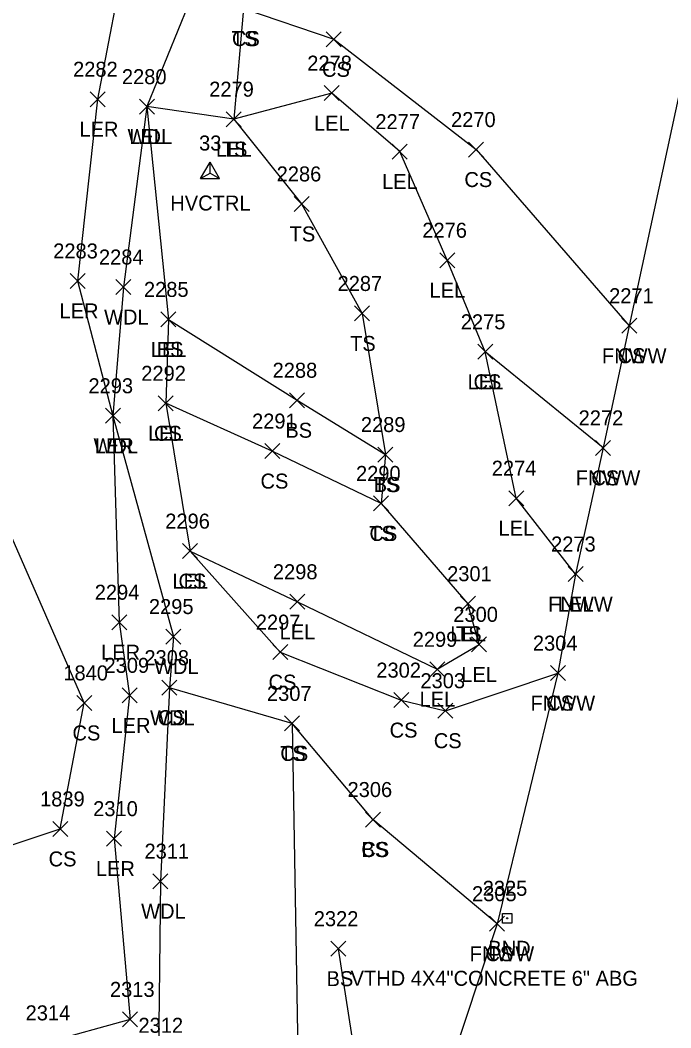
# Model space of a CAD drawing. Extents: x 1483143 to 1488182, y 802902 to 807581.
# Drawn here: x 1487923.7 to 1488010.4, y 806404.6 to 806539 of the extents above; entities that cross this region are included whole.
import ezdxf

# ---------------------------------------------------------------- set-up
doc = ezdxf.new("R2010")
doc.units = 0
for name, color, linetype in [('C_A', 7, 'Continuous'), ('C_I', 7, 'Continuous'), ('CPSM', 7, 'Continuous'), ('L_A', 7, 'Continuous'), ('L_I', 7, 'Continuous'), ('L_TIC', 7, 'Continuous'), ('LARO', 7, 'Continuous'), ('LAWA', 7, 'Continuous'), ('LELB', 7, 'Continuous'), ('LFNC', 7, 'Continuous'), ('M_A', 7, 'Continuous'), ('M_C', 7, 'Continuous'), ('M_I', 7, 'Continuous'), ('MHBP', 7, 'Continuous')]:
    doc.layers.add(name, color=color, linetype=linetype)

msp = doc.modelspace()

# ---------------------------------------------------------------- linework, layer by layer
at = {"layer": 'CPSM'}
for p, q in [((1487947.73, 806517.89), (1487948.98, 806520.06)), ((1487950.23, 806517.89), (1487948.98, 806520.06)), ((1487948.98, 806518.61), (1487948.98, 806520.06)), ((1487947.73, 806517.89), (1487948.98, 806518.61)), ((1487948.98, 806518.61), (1487948.98, 806518.61)), ((1487948.98, 806518.61), (1487950.23, 806517.89)), ((1487947.73, 806517.89), (1487950.23, 806517.89))]:
    msp.add_line(p, q, dxfattribs=at)
at = {"layer": 'L_TIC'}
for points in [[(1487964.47, 806535.44), (1487966.47, 806537.44)], [(1487966.47, 806535.44), (1487964.47, 806537.44)], [(1487964.2, 806528.26), (1487966.2, 806530.26)], [(1487966.2, 806528.26), (1487964.2, 806530.26)], [(1487932.98, 806527.45), (1487934.98, 806529.45)], [(1487934.98, 806527.45), (1487932.98, 806529.45)], [(1487939.57, 806526.46), (1487941.57, 806528.46)], [(1487941.57, 806526.46), (1487939.57, 806528.46)], [(1487939.57, 806526.46), (1487941.57, 806528.46)], [(1487941.57, 806526.46), (1487939.57, 806528.46)], [(1487951.14, 806524.79), (1487953.14, 806526.79)], [(1487953.14, 806524.79), (1487951.14, 806526.79)], [(1487951.14, 806524.79), (1487953.14, 806526.79)], [(1487953.14, 806524.79), (1487951.14, 806526.79)], [(1487973.28, 806520.46), (1487975.28, 806522.46)], [(1487975.28, 806520.46), (1487973.28, 806522.46)], [(1487983.45, 806520.74), (1487985.45, 806522.74)], [(1487985.45, 806520.74), (1487983.45, 806522.74)], [(1487960.18, 806513.49), (1487962.18, 806515.49)], [(1487962.18, 806513.49), (1487960.18, 806515.49)], [(1487979.6, 806505.98), (1487981.6, 806507.98)], [(1487981.6, 806505.98), (1487979.6, 806507.98)], [(1487930.33, 806503.22), (1487932.33, 806505.22)], [(1487932.33, 806503.22), (1487930.33, 806505.22)], [(1487936.43, 806502.41), (1487938.43, 806504.41)], [(1487938.43, 806502.41), (1487936.43, 806504.41)], [(1487968.24, 806498.88), (1487970.24, 806500.88)], [(1487970.24, 806498.88), (1487968.24, 806500.88)], [(1487942.43, 806498.09), (1487944.43, 806500.09)], [(1487944.43, 806498.09), (1487942.43, 806500.09)], [(1487942.43, 806498.09), (1487944.43, 806500.09)], [(1487944.43, 806498.09), (1487942.43, 806500.09)], [(1488003.88, 806497.25), (1488005.88, 806499.25)], [(1488005.88, 806497.25), (1488003.88, 806499.25)], [(1488003.88, 806497.25), (1488005.88, 806499.25)], [(1488005.88, 806497.25), (1488003.88, 806499.25)], [(1487984.67, 806493.77), (1487986.67, 806495.77)], [(1487986.67, 806493.77), (1487984.67, 806495.77)], [(1487984.67, 806493.77), (1487986.67, 806495.77)], [(1487986.67, 806493.77), (1487984.67, 806495.77)], [(1487942.07, 806486.9), (1487944.07, 806488.9)], [(1487944.07, 806486.9), (1487942.07, 806488.9)], [(1487942.07, 806486.9), (1487944.07, 806488.9)], [(1487944.07, 806486.9), (1487942.07, 806488.9)], [(1487959.58, 806487.31), (1487961.58, 806489.31)], [(1487961.58, 806487.31), (1487959.58, 806489.31)], [(1487935.03, 806485.24), (1487937.03, 806487.24)], [(1487937.03, 806485.24), (1487935.03, 806487.24)], [(1487935.03, 806485.24), (1487937.03, 806487.24)], [(1487937.03, 806485.24), (1487935.03, 806487.24)], [(1487956.27, 806480.53), (1487958.27, 806482.53)], [(1487958.27, 806480.53), (1487956.27, 806482.53)], [(1487971.36, 806480.07), (1487973.36, 806482.07)], [(1487973.36, 806480.07), (1487971.36, 806482.07)], [(1487971.36, 806480.07), (1487973.36, 806482.07)], [(1487973.36, 806480.07), (1487971.36, 806482.07)], [(1488000.38, 806480.96), (1488002.38, 806482.96)], [(1488002.38, 806480.96), (1488000.38, 806482.96)], [(1488000.38, 806480.96), (1488002.38, 806482.96)], [(1488002.38, 806480.96), (1488000.38, 806482.96)], [(1487970.79, 806473.55), (1487972.79, 806475.55)], [(1487972.79, 806473.55), (1487970.79, 806475.55)], [(1487970.79, 806473.55), (1487972.79, 806475.55)], [(1487972.79, 806473.55), (1487970.79, 806475.55)], [(1487988.8, 806474.25), (1487990.8, 806476.25)], [(1487990.8, 806474.25), (1487988.8, 806476.25)], [(1487945.33, 806467.19), (1487947.33, 806469.19)], [(1487947.33, 806467.19), (1487945.33, 806469.19)], [(1487945.33, 806467.19), (1487947.33, 806469.19)], [(1487947.33, 806467.19), (1487945.33, 806469.19)], [(1487996.71, 806464.14), (1487998.71, 806466.14)], [(1487998.71, 806464.14), (1487996.71, 806466.14)], [(1487996.71, 806464.14), (1487998.71, 806466.14)], [(1487998.71, 806464.14), (1487996.71, 806466.14)], [(1487959.62, 806460.44), (1487961.62, 806462.44)], [(1487961.62, 806460.44), (1487959.62, 806462.44)], [(1487982.36, 806460.18), (1487984.36, 806462.18)], [(1487984.36, 806460.18), (1487982.36, 806462.18)], [(1487982.36, 806460.18), (1487984.36, 806462.18)], [(1487984.36, 806460.18), (1487982.36, 806462.18)], [(1487935.87, 806457.71), (1487937.87, 806459.71)], [(1487937.87, 806457.71), (1487935.87, 806459.71)], [(1487943.09, 806455.8), (1487945.09, 806457.8)], [(1487945.09, 806455.8), (1487943.09, 806457.8)], [(1487983.84, 806454.76), (1487985.84, 806456.76)], [(1487985.84, 806454.76), (1487983.84, 806456.76)], [(1487957.34, 806453.72), (1487959.34, 806455.72)], [(1487959.34, 806453.72), (1487957.34, 806455.72)], [(1487978.27, 806451.43), (1487980.27, 806453.43)], [(1487980.27, 806451.43), (1487978.27, 806453.43)], [(1487994.36, 806450.92), (1487996.36, 806452.92)], [(1487996.36, 806450.92), (1487994.36, 806452.92)], [(1487994.36, 806450.92), (1487996.36, 806452.92)], [(1487996.36, 806450.92), (1487994.36, 806452.92)], [(1487942.56, 806448.98), (1487944.56, 806450.98)], [(1487944.56, 806448.98), (1487942.56, 806450.98)], [(1487942.56, 806448.98), (1487944.56, 806450.98)], [(1487944.56, 806448.98), (1487942.56, 806450.98)], [(1487937.26, 806447.96), (1487939.26, 806449.96)], [(1487939.26, 806447.96), (1487937.26, 806449.96)], [(1487931.2, 806446.95), (1487933.2, 806448.95)], [(1487933.2, 806446.95), (1487931.2, 806448.95)], [(1487973.48, 806447.32), (1487975.48, 806449.32)], [(1487975.48, 806447.32), (1487973.48, 806449.32)], [(1487979.36, 806445.91), (1487981.36, 806447.91)], [(1487981.36, 806445.91), (1487979.36, 806447.91)], [(1487958.91, 806444.22), (1487960.91, 806446.22)], [(1487960.91, 806444.22), (1487958.91, 806446.22)], [(1487958.91, 806444.22), (1487960.91, 806446.22)], [(1487960.91, 806444.22), (1487958.91, 806446.22)], [(1487969.7, 806431.4), (1487971.7, 806433.4)], [(1487971.7, 806431.4), (1487969.7, 806433.4)], [(1487969.7, 806431.4), (1487971.7, 806433.4)], [(1487971.7, 806431.4), (1487969.7, 806433.4)], [(1487928.02, 806430.15), (1487930.02, 806432.15)], [(1487930.02, 806430.15), (1487928.02, 806432.15)], [(1487935.18, 806428.85), (1487937.18, 806430.85)], [(1487937.18, 806428.85), (1487935.18, 806430.85)], [(1487941.37, 806423.18), (1487943.37, 806425.18)], [(1487943.37, 806423.18), (1487941.37, 806425.18)], [(1487986.25, 806417.51), (1487988.25, 806419.51)], [(1487988.25, 806417.51), (1487986.25, 806419.51)], [(1487986.25, 806417.51), (1487988.25, 806419.51)], [(1487988.25, 806417.51), (1487986.25, 806419.51)], [(1487965.07, 806414.18), (1487967.07, 806416.18)], [(1487967.07, 806414.18), (1487965.07, 806416.18)], [(1487937.33, 806404.75), (1487939.33, 806406.75)], [(1487939.33, 806404.75), (1487937.33, 806406.75)]]:
    msp.add_lwpolyline(points, dxfattribs=at)
at = {"layer": 'LARO'}
for points in [[(1488009.53, 806779.63), (1488008.11, 806762.07), (1487997.19, 806745.28), (1487993.76, 806718.32), (1487985.65, 806695.01), (1487979.99, 806668.22), (1487974.36, 806655.69), (1487966.68, 806636.04), (1487956.68, 806612.98), (1487949.83, 806572.43), (1487937.7, 806551.52), (1487937.93, 806549.12), (1487933.98, 806528.45), (1487931.33, 806504.22), (1487936.03, 806486.24), (1487936.87, 806458.71), (1487938.26, 806448.96), (1487936.18, 806429.85), (1487938.33, 806405.75), (1487927.08, 806402.62)], [(1487997.71, 806465.14), (1487989.8, 806475.25), (1487985.67, 806494.77), (1487980.6, 806506.98), (1487974.28, 806521.46), (1487965.2, 806529.26), (1487952.14, 806525.79), (1487940.57, 806527.46), (1487943.43, 806499.09), (1487943.07, 806487.9), (1487946.33, 806468.19), (1487960.62, 806461.44), (1487979.27, 806452.43), (1487984.84, 806455.76), (1487983.36, 806461.18)]]:
    msp.add_lwpolyline(points, dxfattribs=at)
at = {"layer": 'LAWA'}
msp.add_lwpolyline([(1488013.56, 806779), (1488014.78, 806760.28), (1488003.55, 806746.14), (1488000.09, 806716.32), (1487996.76, 806693.07), (1487992.04, 806662.06), (1487979.2, 806652.61), (1487971.73, 806641.22), (1487963.74, 806612.04), (1487955.87, 806570.61), (1487948.83, 806547.8), (1487940.57, 806527.46), (1487937.43, 806503.41), (1487936.03, 806486.24), (1487944.09, 806456.8), (1487943.56, 806449.98), (1487942.37, 806424.18), (1487942.13, 806400.96)], dxfattribs=at)
at = {"layer": 'LELB'}
for points in [[(1488039.63, 806814.37), (1488031.14, 806790.78), (1488032.93, 806764.39), (1488017.53, 806734.89), (1488014.76, 806696.96), (1488001.7, 806658.62), (1487995.09, 806633.92), (1487984.98, 806604.57), (1487980.48, 806572.93), (1487969.96, 806553.52), (1487953.46, 806540.54), (1487965.47, 806536.44), (1487984.45, 806521.74), (1488004.88, 806498.25)], [(1487979.2, 806652.61), (1487985.81, 806636.52), (1487974.39, 806608.03), (1487972.7, 806575.66), (1487965.34, 806560.53), (1487953.46, 806540.54), (1487952.14, 806525.79), (1487961.18, 806514.49), (1487969.24, 806499.88), (1487972.36, 806481.07), (1487971.79, 806474.55), (1487983.36, 806461.18)], [(1487866.81, 806394.33), (1487869.32, 806406.71), (1487875.39, 806429.92), (1487880.88, 806437.08), (1487887.67, 806436.97), (1487892.32, 806431.91), (1487892.34, 806411.86), (1487895, 806426.13), (1487914.7, 806420.72), (1487917.91, 806427.49), (1487929.02, 806431.15), (1487932.2, 806447.95), (1487916.49, 806483.73), (1487915.56, 806508.05), (1487915.88, 806516.64), (1487912.97, 806522.43), (1487915.7, 806531.99), (1487920.99, 806545.5)], [(1487943.43, 806499.09), (1487960.58, 806488.31), (1487972.36, 806481.07)], [(1488001.38, 806481.96), (1487985.67, 806494.77)], [(1487971.79, 806474.55), (1487957.27, 806481.53), (1487943.07, 806487.9)], [(1487946.33, 806468.19), (1487958.34, 806454.72), (1487974.48, 806448.32), (1487980.36, 806446.91), (1487995.36, 806451.92)], [(1487987.25, 806418.51), (1487970.7, 806432.4), (1487959.91, 806445.22), (1487943.56, 806449.98)], [(1487959.91, 806445.22), (1487960.75, 806398.74), (1487951.5, 806373.39), (1487932.63, 806356.69), (1487906.84, 806324.5), (1487908.42, 806310.52), (1487916.06, 806290.13), (1487905.83, 806276.22)], [(1487966.07, 806415.18), (1487969.53, 806392.86), (1487952.94, 806357.28), (1487940.19, 806330.57), (1487921.69, 806320.66), (1487908.42, 806310.52), (1487904.09, 806299.8)]]:
    msp.add_lwpolyline(points, dxfattribs=at)
at = {"layer": 'LFNC'}
msp.add_lwpolyline([(1488105.96, 806931.77), (1488093.97, 806892.24), (1488086.74, 806870.75), (1488078.76, 806844.27), (1488074.64, 806830.72), (1488062.83, 806775.27), (1488057.88, 806751.49), (1488052.32, 806724.88), (1488045.16, 806690.9), (1488036.14, 806648.33), (1488029.99, 806618.82), (1488025.33, 806595.98), (1488015.01, 806545.3), (1488004.88, 806498.25), (1488001.38, 806481.96), (1487997.71, 806465.14), (1487995.36, 806451.92), (1487987.25, 806418.51), (1487973.91, 806378.22)], dxfattribs=at)
at = {"layer": 'MHBP'}
msp.add_lwpolyline([(1487987.96, 806419.85), (1487989.21, 806419.85), (1487989.21, 806418.6), (1487987.96, 806418.6)], close=True, dxfattribs=at)
msp.add_circle((1487988.59, 806419.23), 0.0833, dxfattribs=at)

# ---------------------------------------------------------------- texts
at = {"layer": 'C_A'}
msp.add_text('HVCTRL', height=2, dxfattribs=at).set_placement((1487943.68, 806513.61))
at = {"layer": 'C_I'}
msp.add_text('33', height=2, dxfattribs=at).set_placement((1487947.52, 806521.61))
at = {"layer": 'L_A'}
for s, p in [('TS', (1487951.87, 806535.54)), ('CS', (1487951.9, 806535.54)), ('CS', (1487963.91, 806531.44)), ('LEL', (1487962.84, 806524.26)), ('LER', (1487931.56, 806523.45)), ('WDL', (1487937.99, 806522.46)), ('LEL', (1487938.21, 806522.46)), ('LEL', (1487949.77, 806520.79)), ('TS', (1487950.55, 806520.79)), ('LEL', (1487971.91, 806516.46)), ('CS', (1487982.89, 806516.74)), ('TS', (1487959.59, 806509.49)), ('LEL', (1487978.24, 806501.98)), ('LER', (1487928.91, 806499.22)), ('WDL', (1487934.85, 806498.41)), ('TS', (1487967.65, 806494.88)), ('LEL', (1487941.07, 806494.09)), ('BS', (1487941.88, 806494.09)), ('FNWW', (1488001.23, 806493.25)), ('CS', (1488003.32, 806493.25)), ('LEL', (1487983.31, 806489.77)), ('CS', (1487984.11, 806489.77)), ('LEL', (1487940.71, 806482.9)), ('CS', (1487941.51, 806482.9)), ('BS', (1487959.02, 806483.31)), ('WDL', (1487933.45, 806481.24)), ('LER', (1487933.61, 806481.24)), ('CS', (1487955.71, 806476.53)), ('TS', (1487970.77, 806476.07)), ('BS', (1487970.8, 806476.07)), ('FNWW', (1487997.73, 806476.96)), ('CS', (1487999.82, 806476.96)), ('TS', (1487970.2, 806469.55)), ('CS', (1487970.23, 806469.55)), ('LEL', (1487987.44, 806470.25)), ('LEL', (1487943.97, 806463.19)), ('CS', (1487944.77, 806463.19)), ('FNWW', (1487994.06, 806460.14)), ('LEL', (1487995.35, 806460.14)), ('LEL', (1487958.26, 806456.44)), ('LEL', (1487981, 806456.18)), ('TS', (1487981.77, 806456.18)), ('LER', (1487934.45, 806453.71)), ('WDL', (1487941.51, 806451.8)), ('LEL', (1487982.47, 806450.76)), ('CS', (1487956.78, 806449.72)), ('LEL', (1487976.91, 806447.43)), ('FNWW', (1487991.71, 806446.92)), ('CS', (1487993.8, 806446.92)), ('WDL', (1487940.98, 806444.98)), ('CS', (1487942.01, 806444.98)), ('LER', (1487935.84, 806443.96)), ('CS', (1487930.64, 806442.95)), ('CS', (1487972.92, 806443.32)), ('CS', (1487978.81, 806441.91)), ('TS', (1487958.32, 806440.22)), ('CS', (1487958.35, 806440.22)), ('CS', (1487969.15, 806427.4)), ('BS', (1487969.15, 806427.4)), ('CS', (1487927.46, 806426.15)), ('LER', (1487933.76, 806424.85)), ('WDL', (1487939.79, 806419.18)), ('FNWW', (1487983.59, 806413.51)), ('CS', (1487985.69, 806413.51)), ('BS', (1487964.51, 806410.18))]:
    msp.add_text(s, height=2, dxfattribs=at).set_placement(p)
at = {"layer": 'L_I'}
for s, p in [('2278', (1487961.94, 806532.26)), ('2282', (1487930.72, 806531.45)), ('2280', (1487937.23, 806530.46)), ('2280', (1487937.23, 806530.46)), ('2279', (1487948.87, 806528.79)), ('2279', (1487948.87, 806528.79)), ('2277', (1487971.02, 806524.46)), ('2270', (1487981.11, 806524.74)), ('2286', (1487957.86, 806517.49)), ('2276', (1487977.28, 806509.98)), ('2283', (1487928.07, 806507.22)), ('2284', (1487934.17, 806506.41)), ('2287', (1487965.98, 806502.88)), ('2285', (1487940.17, 806502.09)), ('2285', (1487940.17, 806502.09)), ('2271', (1488002.19, 806501.25)), ('2271', (1488002.19, 806501.25)), ('2275', (1487982.41, 806497.77)), ('2275', (1487982.41, 806497.77)), ('2292', (1487939.81, 806490.9)), ('2292', (1487939.81, 806490.9)), ('2288', (1487957.32, 806491.31)), ('2293', (1487932.77, 806489.24)), ('2293', (1487932.77, 806489.24)), ('2291', (1487954.58, 806484.53)), ('2289', (1487969.09, 806484.07)), ('2289', (1487969.09, 806484.07)), ('2272', (1487998.12, 806484.96)), ('2272', (1487998.12, 806484.96)), ('2290', (1487968.44, 806477.55)), ('2290', (1487968.44, 806477.55)), ('2274', (1487986.54, 806478.25)), ('2296', (1487943.01, 806471.19)), ('2296', (1487943.01, 806471.19)), ('2273', (1487994.45, 806468.14)), ('2273', (1487994.45, 806468.14)), ('2298', (1487957.36, 806464.44)), ('2301', (1487980.59, 806464.18)), ('2301', (1487980.59, 806464.18)), ('2294', (1487933.61, 806461.71)), ('2295', (1487940.83, 806459.8)), ('2300', (1487981.41, 806458.76)), ('2297', (1487955.08, 806457.72)), ('2299', (1487976, 806455.43)), ('2304', (1487992.02, 806454.92)), ('2304', (1487992.02, 806454.92)), ('2308', (1487940.23, 806452.98)), ('2308', (1487940.23, 806452.98)), ('2309', (1487934.91, 806451.96)), ('1840', (1487929.42, 806450.95)), ('2302', (1487971.15, 806451.32)), ('2303', (1487977.03, 806449.91)), ('2307', (1487956.57, 806448.22)), ('2307', (1487956.57, 806448.22)), ('2306', (1487967.31, 806435.4)), ('2306', (1487967.31, 806435.4)), ('1839', (1487926.32, 806434.15)), ('2310', (1487933.4, 806432.85)), ('2311', (1487940.24, 806427.18)), ('2305', (1487983.91, 806421.51)), ('2305', (1487983.91, 806421.51)), ('2322', (1487962.81, 806418.18)), ('2313', (1487935.64, 806408.75)), ('2314', (1487924.39, 806405.62)), ('2312', (1487939.44, 806403.96))]:
    msp.add_text(s, height=2, dxfattribs=at).set_placement(p)
at = {"layer": 'M_A'}
msp.add_text('BND', height=2, dxfattribs=at).set_placement((1487986.08, 806414.23))
at = {"layer": 'M_C'}
msp.add_text('VTHD 4X4"CONCRETE 6" ABG', height=2, dxfattribs=at).set_placement((1487967.72, 806410.23))
at = {"layer": 'M_I'}
msp.add_text('2325', height=2, dxfattribs=at).set_placement((1487985.33, 806422.23))

doc.saveas('drawing.dxf')
